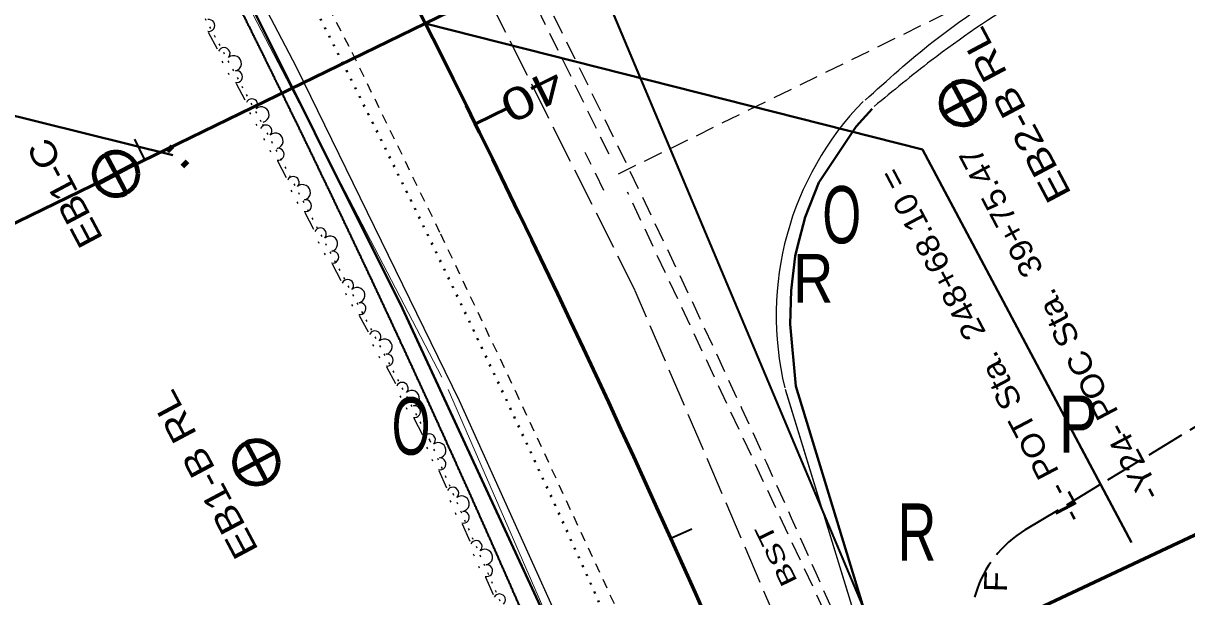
# Model space of a CAD drawing. Extents: x 2402199 to 2404507, y 568050 to 571478.
# Drawn here: x 2402420.4 to 2402674.4, y 570872 to 570997.1 of the extents above; entities that cross this region are included whole.
import ezdxf
from ezdxf.enums import TextEntityAlignment as Align

# ---------------------------------------------------------------- set-up
doc = ezdxf.new("R2010")
doc.units = 0
doc.header["$LTSCALE"] = 1.4
for name, pattern in [('DOTTED', [1.5, 0.3, -1.2]), ('LONG_DASHED', [7.5, 6, -1.5]), ('MEDIUM_DASHED', [4.5, 3, -1.5]), ('SHORT_DASHED', [2.7, 1.5, -1.2])]:
    doc.linetypes.add(name, pattern=pattern)
for name, color, linetype, lineweight in [('1', 7, 'Continuous', 35), ('11', 7, 'Continuous', 25), ('15', 7, 'DOTTED', 40), ('17', 7, 'MEDIUM_DASHED', 35), ('18', 7, 'SHORT_DASHED', 25), ('19', 7, 'Continuous', 35), ('21', 7, 'Continuous', 40), ('27', 7, 'Continuous', 80), ('28', 7, 'Continuous', 25), ('3', 7, 'Continuous', 25), ('42', 7, 'Continuous', 25), ('6', 7, 'Continuous', 35), ('62', 7, 'Continuous', 60), ('63', 7, 'Continuous', 35), ('9', 7, 'Continuous', 13)]:
    doc.layers.add(name, color=color, linetype=linetype, lineweight=lineweight)
for name, color, linetype in [('14', 7, 'Continuous'), ('2', 7, 'Continuous'), ('23', 7, 'Continuous')]:
    doc.layers.add(name, color=color, linetype=linetype)

msp = doc.modelspace()

# ---------------------------------------------------------------- linework, layer by layer
at = {"layer": '1'}
msp.add_line((2402526.719, 571052.414), (2402605.967, 570864.37), dxfattribs=at)
for points in [[(2402475.474, 570984.701), (2402475.081, 570985.499), (2402474.689, 570986.297), (2402474.296, 570987.095), (2402473.903, 570987.893), (2402473.51, 570988.691), (2402473.112, 570989.497), (2402472.718, 570990.294), (2402472.325, 570991.091), (2402471.93, 570991.889), (2402471.536, 570992.685), (2402471.141, 570993.482), (2402470.746, 570994.279), (2402470.351, 570995.076), (2402469.956, 570995.872), (2402469.56, 570996.669), (2402469.164, 570997.465), (2402468.763, 570998.27), (2402468.367, 570999.066), (2402467.97, 570999.861), (2402467.573, 571000.657), (2402467.176, 571001.453), (2402466.779, 571002.249), (2402466.381, 571003.044), (2402465.983, 571003.84), (2402465.585, 571004.634), (2402465.186, 571005.429), (2402464.788, 571006.225), (2402464.385, 571007.028), (2402463.985, 571007.823), (2402463.586, 571008.618), (2402463.186, 571009.412), (2402462.786, 571010.206), (2402462.386, 571011), (2402461.985, 571011.794), (2402461.585, 571012.589), (2402461.184, 571013.382), (2402460.783, 571014.176), (2402460.382, 571014.969), (2402459.975, 571015.772), (2402459.573, 571016.565), (2402459.171, 571017.358), (2402458.769, 571018.152), (2402458.366, 571018.944), (2402457.963, 571019.737), (2402457.56, 571020.53), (2402457.157, 571021.323), (2402456.753, 571022.115), (2402456.349, 571022.907), (2402455.945, 571023.699), (2402455.536, 571024.5), (2402455.131, 571025.293), (2402454.726, 571026.084), (2402454.321, 571026.876), (2402453.916, 571027.668), (2402453.51, 571028.459), (2402453.104, 571029.251), (2402452.698, 571030.042), (2402452.291, 571030.833), (2402451.885, 571031.624), (2402451.478, 571032.415), (2402451.071, 571033.206), (2402450.659, 571034.005), (2402450.251, 571034.796), (2402449.843, 571035.586), (2402449.435, 571036.376), (2402449.027, 571037.167), (2402448.618, 571037.956), (2402448.209, 571038.746), (2402447.8, 571039.536), (2402447.39, 571040.326), (2402446.981, 571041.116), (2402446.571, 571041.904), (2402446.157, 571042.703), (2402445.746, 571043.492)], [(2402503.828, 570925.255), (2402503.454, 570926.062), (2402503.076, 570926.878), (2402502.703, 570927.684), (2402502.328, 570928.491), (2402501.954, 570929.297), (2402501.579, 570930.103), (2402501.203, 570930.909), (2402500.828, 570931.715), (2402500.453, 570932.521), (2402500.077, 570933.327), (2402499.701, 570934.132), (2402499.325, 570934.937), (2402498.944, 570935.752), (2402498.567, 570936.557), (2402498.19, 570937.362), (2402497.812, 570938.167), (2402497.435, 570938.972), (2402497.057, 570939.777), (2402496.679, 570940.581), (2402496.3, 570941.386), (2402495.922, 570942.191), (2402495.543, 570942.994), (2402495.164, 570943.799), (2402494.785, 570944.603), (2402494.4, 570945.416), (2402494.021, 570946.22), (2402493.641, 570947.023), (2402493.26, 570947.827), (2402492.88, 570948.63), (2402492.499, 570949.434), (2402492.118, 570950.237), (2402491.736, 570951.04), (2402491.354, 570951.843), (2402490.973, 570952.646), (2402490.591, 570953.449), (2402490.204, 570954.26), (2402489.821, 570955.063), (2402489.438, 570955.865), (2402489.055, 570956.667), (2402488.672, 570957.47), (2402488.288, 570958.272), (2402487.904, 570959.074), (2402487.52, 570959.876), (2402487.136, 570960.677), (2402486.751, 570961.479), (2402486.366, 570962.28), (2402485.977, 570963.091), (2402485.591, 570963.892), (2402485.206, 570964.694), (2402484.82, 570965.494), (2402484.433, 570966.295), (2402484.047, 570967.096), (2402483.661, 570967.897), (2402483.274, 570968.697), (2402482.887, 570969.498), (2402482.499, 570970.298), (2402482.111, 570971.098), (2402481.719, 570971.907), (2402481.331, 570972.707), (2402480.942, 570973.507), (2402480.554, 570974.307), (2402480.165, 570975.106), (2402479.775, 570975.905), (2402479.386, 570976.706), (2402478.996, 570977.505), (2402478.606, 570978.304), (2402478.216, 570979.103), (2402477.826, 570979.901), (2402477.431, 570980.709), (2402477.04, 570981.508), (2402476.649, 570982.306), (2402476.257, 570983.105), (2402475.865, 570983.903), (2402475.473, 570984.702)], [(2402530.791, 570865.196), (2402530.436, 570866.011), (2402530.081, 570866.826), (2402529.726, 570867.64), (2402529.371, 570868.455), (2402529.015, 570869.269), (2402528.659, 570870.084), (2402528.303, 570870.898), (2402527.946, 570871.712), (2402527.589, 570872.526), (2402527.228, 570873.349), (2402526.871, 570874.163), (2402526.513, 570874.976), (2402526.155, 570875.791), (2402525.798, 570876.603), (2402525.439, 570877.417), (2402525.081, 570878.23), (2402524.722, 570879.043), (2402524.363, 570879.856), (2402524.004, 570880.669), (2402523.644, 570881.482), (2402523.28, 570882.304), (2402522.92, 570883.117), (2402522.56, 570883.929), (2402522.199, 570884.742), (2402521.838, 570885.554), (2402521.477, 570886.366), (2402521.115, 570887.178), (2402520.754, 570887.99), (2402520.392, 570888.802), (2402520.03, 570889.613), (2402519.668, 570890.425), (2402519.301, 570891.246), (2402518.938, 570892.057), (2402518.575, 570892.868), (2402518.212, 570893.679), (2402517.848, 570894.491), (2402517.484, 570895.302), (2402517.12, 570896.113), (2402516.755, 570896.924), (2402516.391, 570897.734), (2402516.026, 570898.544), (2402515.661, 570899.355), (2402515.291, 570900.174), (2402514.925, 570900.984), (2402514.559, 570901.794), (2402514.193, 570902.604), (2402513.827, 570903.414), (2402513.46, 570904.223), (2402513.093, 570905.034), (2402512.726, 570905.843), (2402512.358, 570906.652), (2402511.99, 570907.462), (2402511.623, 570908.271), (2402511.251, 570909.089), (2402510.882, 570909.898), (2402510.513, 570910.707), (2402510.144, 570911.515), (2402509.775, 570912.324), (2402509.405, 570913.132), (2402509.035, 570913.941), (2402508.666, 570914.749), (2402508.295, 570915.557), (2402507.925, 570916.366), (2402507.554, 570917.173), (2402507.179, 570917.99), (2402506.807, 570918.798), (2402506.436, 570919.606), (2402506.064, 570920.413), (2402505.692, 570921.22), (2402505.32, 570922.028), (2402504.947, 570922.835), (2402504.575, 570923.642), (2402504.201, 570924.449), (2402503.828, 570925.256)]]:
    msp.add_spline(points, degree=3, dxfattribs=at)
at = {"layer": '11'}
for p, q in [((2402460.745, 570995.182), (2402462.697, 570991.575)), ((2402463.703, 570988.856), (2402463.899, 570988.495)), ((2402465.07, 570986.33), (2402465.265, 570985.97)), ((2402466.798, 570984.002), (2402468.75, 570980.395)), ((2402469.757, 570977.676), (2402469.952, 570977.315)), ((2402471.123, 570975.151), (2402471.319, 570974.791)), ((2402472.815, 570971.97), (2402473.007, 570971.607)), ((2402474.161, 570969.431), (2402474.353, 570969.069)), ((2402475.866, 570967.088), (2402477.785, 570963.464)), ((2402478.766, 570960.735), (2402478.958, 570960.373)), ((2402480.11, 570958.199), (2402480.302, 570957.836)), ((2402481.816, 570955.853), (2402483.735, 570952.23)), ((2402484.717, 570949.501), (2402484.908, 570949.139)), ((2402486.061, 570946.964), (2402486.253, 570946.601)), ((2402487.767, 570944.619), (2402489.686, 570940.995)), ((2402490.668, 570938.265), (2402490.86, 570937.903)), ((2402492.012, 570935.728), (2402492.204, 570935.366)), ((2402493.717, 570933.385), (2402495.637, 570929.76)), ((2402496.618, 570927.031), (2402496.81, 570926.669)), ((2402497.962, 570924.495), (2402498.154, 570924.132)), ((2402499.668, 570922.15), (2402501.587, 570918.526)), ((2402502.568, 570915.797), (2402502.76, 570915.434)), ((2402503.913, 570913.26), (2402504.104, 570912.897)), ((2402505.619, 570910.915), (2402507.538, 570907.292)), ((2402508.407, 570904.608), (2402508.572, 570904.233)), ((2402509.557, 570901.978), (2402509.722, 570901.603)), ((2402511.084, 570899.514), (2402512.728, 570895.757)), ((2402513.502, 570892.965), (2402513.666, 570892.588)), ((2402514.653, 570890.334), (2402514.817, 570889.958)), ((2402516.18, 570887.867), (2402517.824, 570884.11)), ((2402518.599, 570881.314), (2402518.764, 570880.938)), ((2402519.75, 570878.684), (2402519.915, 570878.309)), ((2402521.277, 570876.22), (2402522.921, 570872.463))]:
    msp.add_line(p, q, dxfattribs=at)
at = {"layer": '11', "linetype": 'DOTTED'}
for points in [[(2402402.474, 571095.885), (2402413.129, 571099.725), (2402421.048, 571070.224), (2402472.559, 570975.083)], [(2402472.559, 570975.083), (2402509.097, 570906.101), (2402545.728, 570822.387)]]:
    msp.add_lwpolyline(points, dxfattribs=at)
at = {"layer": '11'}
for centre, radius, start, end in [((2402460.88, 570996.654), 1.297, 259.20044, 99.99701), ((2402464.2, 570990.523), 1.297, 316.86691, 157.66348), ((2402466.288, 570988.389), 1.691, 284.39572, 132.46821), ((2402466.933, 570985.474), 1.297, 259.20044, 99.99701), ((2402470.253, 570979.343), 1.297, 316.86691, 157.66348), ((2402472.341, 570977.209), 1.691, 284.39572, 132.46821), ((2402473.327, 570973.633), 1.297, 316.34386, 157.14043), ((2402475.396, 570971.48), 1.691, 283.87267, 131.94516), ((2402476.015, 570968.559), 1.297, 258.67739, 99.47396), ((2402479.278, 570962.398), 1.297, 316.34386, 157.14043), ((2402481.346, 570960.245), 1.691, 283.87267, 131.94516), ((2402481.965, 570957.325), 1.297, 258.67739, 99.47396), ((2402485.228, 570951.164), 1.297, 316.34386, 157.14043), ((2402487.297, 570949.011), 1.691, 283.87267, 131.94516), ((2402487.916, 570946.09), 1.297, 258.67739, 99.47396), ((2402491.179, 570939.929), 1.297, 316.34386, 157.14043), ((2402493.248, 570937.776), 1.691, 283.87267, 131.94516), ((2402493.867, 570934.855), 1.297, 258.67739, 99.47396), ((2402497.13, 570928.694), 1.297, 316.34386, 157.14043), ((2402499.198, 570926.542), 1.691, 283.87267, 131.94516), ((2402499.817, 570923.621), 1.297, 258.67739, 99.47396), ((2402503.08, 570917.46), 1.297, 316.34386, 157.14043), ((2402505.149, 570915.307), 1.691, 283.87267, 131.94516), ((2402505.768, 570912.386), 1.297, 258.67739, 99.47396), ((2402509.031, 570906.225), 1.297, 316.34386, 157.14043), ((2402510.943, 570903.929), 1.691, 279.59664, 127.66913), ((2402511.342, 570900.97), 1.297, 254.40136, 95.19793), ((2402514.137, 570894.583), 1.297, 312.06783, 152.8644), ((2402516.039, 570892.282), 1.691, 279.59664, 127.66913), ((2402516.439, 570889.323), 1.297, 254.40136, 95.19793), ((2402519.233, 570882.936), 1.297, 312.06783, 152.8644), ((2402521.136, 570880.635), 1.691, 279.59664, 127.66913), ((2402521.535, 570877.676), 1.297, 254.40136, 95.19793), ((2402524.33, 570871.289), 1.297, 312.06783, 152.8644)]:
    msp.add_arc(centre, radius, start, end, dxfattribs=at)
at = {"layer": '15'}
msp.add_arc((2399911.332, 569690.208), 2887.133, 22.84472, 37.57762, dxfattribs=at)
at = {"layer": '17', "lineweight": 25}
for p, q in [((2402548.257, 570968.542), (2402505.556, 571055.624)), ((2402550.332, 570964.289), (2402655.74, 571015.937)), ((2402547.099, 570960.663), (2402543.057, 570968.914)), ((2402616.8, 570822.931), (2402552.299, 570960.292))]:
    msp.add_line(p, q, dxfattribs=at)
at = {"layer": '17', "linetype": 'LONG_DASHED'}
msp.add_line((2402639.183, 570886.623), (2402692.803, 570919.098), dxfattribs=at)
at = {"layer": '17', "linetype": 'Continuous', "lineweight": 60}
msp.add_line((2402707.695, 570900.235), (2402626.394, 570862.088), dxfattribs=at)
at = {"layer": '17', "lineweight": 25}
msp.add_arc((2399953.615, 569708.021), 2887.133, 22.84472, 31.18511, dxfattribs=at)
at = {"layer": '17', "linetype": 'LONG_DASHED'}
msp.add_arc((2402652.134, 570865.24), 25, 121.20094, 203.74382, dxfattribs=at)
at = {"layer": '18'}
msp.add_lwpolyline([(2402476.431, 571020.802), (2402492.105, 570990.812), (2402511.433, 570951.178), (2402527.751, 570916.956), (2402550.218, 570868.56), (2402584.143, 570790.967), (2402591.502, 570773.916)], dxfattribs=at)
at = {"layer": '19', "linetype": 'LONG_DASHED', "lineweight": 25}
msp.add_line((2402618.477, 570788.259), (2402553.966, 570938.719), dxfattribs=at)
msp.add_lwpolyline([(2402553.96, 570938.781), (2402489.547, 571067.152), (2402430.056, 571174.439), (2402385.495, 571247.202)], dxfattribs=at)
at = {"layer": '21'}
msp.add_line((2402453.011, 570968.339), (2402374.495, 570987.785), dxfattribs=at)
for points in [[(2402571.932, 570780.533), (2402538.299, 570859.007), (2402503.143, 570934.851), (2402464.804, 571011.777), (2402426.113, 571084.024), (2402384.214, 571156.832), (2402372.534, 571175.865)], [(2402605.193, 570865.012), (2402589.054, 570917.907), (2402587.809, 570931.49), (2402588.036, 570938.82), (2402588.896, 570946.33), (2402589.348, 570948.395), (2402591.028, 570954.851), (2402594.052, 570962.351), (2402602.158, 570974.597), (2402605.678, 570978.446)]]:
    msp.add_lwpolyline(points, dxfattribs=at)
at = {"layer": '27'}
for p, q in [((2402623.252, 570983.915), (2402627.706, 570975.539)), ((2402629.666, 570981.954), (2402621.291, 570977.502)), ((2402621.266, 570977.548), (2402621.291, 570977.502)), ((2402438.377, 570968.442), (2402442.831, 570960.066)), ((2402444.792, 570966.481), (2402436.416, 570962.029)), ((2402436.391, 570962.075), (2402436.416, 570962.029)), ((2402469.013, 570905.502), (2402473.466, 570897.126)), ((2402475.428, 570903.541), (2402467.052, 570899.089)), ((2402467.027, 570899.135), (2402467.052, 570899.089))]:
    msp.add_line(p, q, dxfattribs=at)
for points in [[(2402629.666, 570981.954), (2402625.478, 570979.728), (2402623.252, 570983.915), (2402623.206, 570983.89)], [(2402621.291, 570977.502), (2402625.478, 570979.728), (2402627.706, 570975.539)], [(2402444.792, 570966.481), (2402440.604, 570964.255), (2402438.377, 570968.442), (2402438.331, 570968.417)], [(2402436.416, 570962.029), (2402440.604, 570964.255), (2402442.831, 570960.066)], [(2402475.428, 570903.541), (2402471.239, 570901.315), (2402469.013, 570905.502), (2402468.966, 570905.477)], [(2402467.052, 570899.089), (2402471.239, 570901.315), (2402473.466, 570897.126)]]:
    msp.add_lwpolyline(points, dxfattribs=at)
for centre in [(2402625.478, 570979.728), (2402440.604, 570964.255), (2402471.239, 570901.314)]:
    msp.add_circle(centre, 4.743, dxfattribs=at)
for centre, start, end in [((2402625.478, 570979.728), 28, 118.64427), ((2402625.478, 570979.728), 207.35574, 298), ((2402440.604, 570964.255), 28, 118.64427), ((2402440.604, 570964.255), 207.35574, 298), ((2402471.239, 570901.314), 28, 118.64427), ((2402471.239, 570901.314), 207.35574, 298)]:
    msp.add_arc(centre, 4.743, start, end, dxfattribs=at)
at = {"layer": '28'}
msp.add_line((2402603.145, 570863.853), (2402586.729, 570917.175), dxfattribs=at)
msp.add_lwpolyline([(2402374.812, 571177.076), (2402399.705, 571135.603), (2402440.232, 571063.522), (2402479.967, 570987.625), (2402515.512, 570914.776), (2402552.113, 570833.795), (2402574.37, 570781.072)], dxfattribs=at)
msp.add_ellipse((2402651.713, 570933.349), major_axis=(-45.019, -49.609), ratio=0.999993, start_param=4.6772796, end_param=5.6872778, dxfattribs=at)
msp.add_spline([(2402672.797, 571021.249), (2402662.311, 571016.13), (2402638.421, 571002.609), (2402618.59, 570989.004), (2402606.097, 570978.965)], degree=3, dxfattribs=at)
at = {"layer": '3', "lineweight": 35}
msp.add_line((2402526.719, 571052.414), (2402619.911, 570831.283), dxfattribs=at)
at = {"layer": '3'}
msp.add_line((2402603.38, 570863.206), (2402586.846, 570916.911), dxfattribs=at)
msp.add_lwpolyline([(2402374.812, 571177.076), (2402399.705, 571135.603), (2402440.232, 571063.522), (2402479.967, 570987.625), (2402515.512, 570914.776), (2402552.113, 570833.795), (2402574.37, 570781.072)], dxfattribs=at)
at = {"layer": '3', "lineweight": 40}
for points in [[(2402571.932, 570780.533), (2402538.299, 570859.007), (2402503.143, 570934.851), (2402464.804, 571011.777), (2402426.113, 571084.024), (2402384.214, 571156.832), (2402372.534, 571175.865)], [(2402605.193, 570865.012), (2402589.054, 570917.907), (2402587.809, 570931.49), (2402588.036, 570938.82), (2402588.896, 570946.33), (2402589.348, 570948.395), (2402591.028, 570954.851), (2402594.052, 570962.351), (2402602.158, 570974.597), (2402605.678, 570978.446)]]:
    msp.add_lwpolyline(points, dxfattribs=at)
at = {"layer": '3'}
msp.add_ellipse((2402651.713, 570933.349), major_axis=(-45.019, -49.609), ratio=0.999993, start_param=4.6772796, end_param=5.6872778, dxfattribs=at)
at = {"layer": '42'}
msp.add_spline([(2402604.139, 570980.327), (2402619.016, 570993.164), (2402638.22, 571006.292), (2402658.089, 571017.786), (2402671.023, 571024.586)], degree=3, dxfattribs=at)
at = {"layer": '6', "lineweight": 13}
for p, q in [((2402415.453, 571105.055), (2402511.71, 570919.872)), ((2402513.131, 570917.239), (2402578.519, 570767.013))]:
    msp.add_line(p, q, dxfattribs=at)
at = {"layer": '6', "lineweight": 60}
msp.add_line((2402519.075, 570975.167), (2402526.25, 570978.706), dxfattribs=at)
at = {"layer": '6'}
for p, q in [((2402446.898, 570967.32), (2402444.709, 570971.816)), ((2402561.751, 570884.735), (2402566.308, 570886.79))]:
    msp.add_line(p, q, dxfattribs=at)
at = {"layer": '62'}
msp.add_line((2402379.217, 570934.377), (2402649.132, 571065.756), dxfattribs=at)
msp.add_arc((2399929.798, 569697.989), 2887.133, 22.84477, 31.13893, dxfattribs=at)
at = {"layer": '63', "lineweight": 40}
for p, q in [((2402508.129, 570997.124), (2402616.674, 570969.599)), ((2402616.674, 570969.599), (2402662.278, 570883.829))]:
    msp.add_line(p, q, dxfattribs=at)

# ---------------------------------------------------------------- texts
at = {"layer": '14'}
for s, height, width, p in [('R', 10.66, 0.85, (2402592.825, 570936.126)), ('P', 12.5, 0.75, (2402650.68, 570903.391)), ('R', 12.5, 0.7, (2402615.465, 570879.836))]:
    msp.add_text(s, height=height, dxfattribs=dict(at, width=width)).set_placement(p, align=Align.CENTER)
at = {"layer": '17', "width": 1.1}
msp.add_text('F', height=5, rotation=88.247, dxfattribs=at).set_placement((2402635.133, 570875.183), align=Align.CENTER)
at = {"layer": '2', "width": 1.65}
msp.add_text(':', height=7.5, rotation=45, dxfattribs=at).set_placement((2402456.039, 570966.063), align=Align.CENTER)
at = {"layer": '23', "width": 1.5}
msp.add_text('US 258    BST', height=3.691, rotation=115.818, dxfattribs=at).set_placement((2402593.5, 570867.019), align=Align.CENTER)
at = {"layer": '27'}
for s, width, p in [('EB2-B RL', 1.25, (2402639.5, 570978.397)), ('EB1-C', 1.15, (2402431.926, 570961.377)), ('EB1-B RL', 1.2, (2402462.404, 570899.918))]:
    msp.add_text(s, height=5.625, rotation=118, dxfattribs=dict(at, width=width)).set_placement(p, align=Align.CENTER)
at = {"layer": '63', "width": 1.35}
msp.add_text('40', height=7, rotation=206.255, dxfattribs=at).set_placement((2402530.028, 570984.448), align=Align.CENTER)
at = {"layer": '63', "width": 1.1}
for s, rotation, p in [('-Y24- POC Sta.  39+75.47', 117.733, (2402628.838, 570970.708)), ('-L- POT Sta.  248+68.10 =', 117.741, (2402611.403, 570966.22))]:
    msp.add_text(s, height=5, rotation=rotation, dxfattribs=at).set_placement(p, align=Align.RIGHT)
at = {"layer": '9', "width": 0.65}
for p in [(2402599.044, 570949.103), (2402505.015, 570902.983)]:
    msp.add_text('O', height=12.5, dxfattribs=at).set_placement(p, align=Align.CENTER)

doc.saveas('drawing.dxf')
